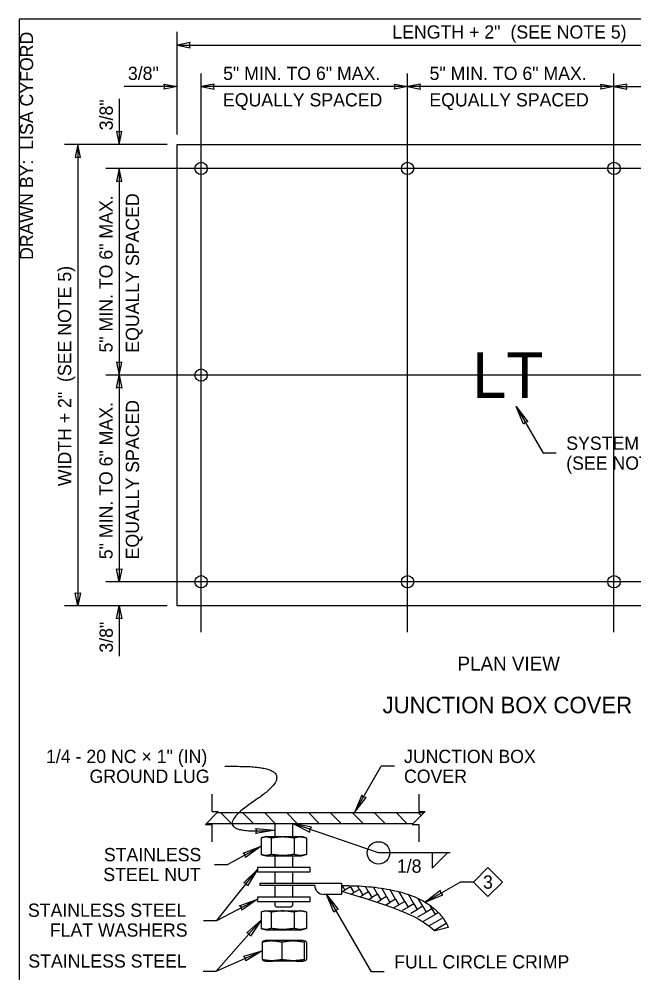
# Model space of a CAD drawing. Extents: x 99862 to 103680, y 99470 to 102076.
# Drawn here: x 99862 to 100605, y 100923 to 102076 of the extents above; entities that cross this region are included whole.
import ezdxf

# ---------------------------------------------------------------- set-up
doc = ezdxf.new("R2010")
doc.units = 0
for name, color, linetype in [('Level 1', 7, 'Continuous'), ('Level 10', 7, 'Continuous'), ('Level 11', 7, 'Continuous'), ('Level 13', 7, 'Continuous'), ('Level 15', 7, 'Continuous'), ('Level 16', 7, 'Continuous'), ('Level 20', 7, 'Continuous'), ('Level 62', 7, 'Continuous')]:
    doc.layers.add(name, color=color, linetype=linetype)

msp = doc.modelspace()

# ---------------------------------------------------------------- linework, layer by layer
at = {"layer": 'Level 1'}
for p, q in [((100101.6, 101116.4), (100351.5, 101116.4)), ((100105.5, 101116.4), (100118.7, 101103.3)), ((100132, 101116.4), (100145.2, 101103.3)), ((100158.6, 101116.4), (100171.7, 101103.3)), ((100185.1, 101116.4), (100198.2, 101103.3)), ((100211.6, 101116.4), (100224.8, 101103.3)), ((100238.1, 101116.4), (100251.3, 101103.3)), ((100264.6, 101116.4), (100277.8, 101103.3)), ((100291.1, 101116.4), (100304.3, 101103.3)), ((100317.7, 101116.4), (100330.8, 101103.3)), ((100344.2, 101116.4), (100347.8, 101112.8)), ((100088.4, 101103.3), (100338.3, 101103.3))]:
    msp.add_line(p, q, dxfattribs=at)
msp.add_lwpolyline([(99862, 99999.5), (103151, 99999.5), (103151, 102075.5), (99862, 102075.5)], close=True, dxfattribs=at)
msp.add_lwpolyline([(99862, 99999.5), (103151, 99999.5), (103151, 102075.5), (99862, 102075.5)], close=True, dxfattribs=at)
msp.add_lwpolyline([(99862, 99999.5), (103151, 99999.5), (103151, 102075.5), (99862, 102075.5)], close=True, dxfattribs=at)
at = {"layer": 'Level 10'}
for p, q in [((100171, 101103.3), (100171, 101087.4)), ((100192.9, 101087.4), (100192.9, 101103.3)), ((100155.1, 101085.9), (100154.4, 101085.6)), ((100154.4, 101085.6), (100154.4, 101065.9)), ((100160.5, 101087.4), (100155.1, 101085.9)), ((100160.5, 101087.4), (100203.4, 101087.4)), ((100166.8, 101085.6), (100166.8, 101065.9)), ((100194.4, 101085.6), (100194.4, 101065.9)), ((100208.8, 101085.9), (100203.4, 101087.4)), ((100208.8, 101085.9), (100209.5, 101085.6)), ((100209.5, 101085.6), (100209.5, 101065.9)), ((100154.3, 101065.9), (100160.5, 101064.2)), ((100208.8, 101065.7), (100209.5, 101065.9)), ((100160.5, 101064.2), (100203.4, 101064.2)), ((100171, 101064.2), (100171, 101050.3)), ((100192.9, 101050.3), (100192.9, 101064.2)), ((100203.4, 101064.2), (100208.8, 101065.7)), ((100171, 101045), (100171, 101031.2)), ((100192.9, 101031.2), (100192.9, 101045)), ((100171, 101028.5), (100171, 101014.4)), ((100192.9, 101014.4), (100192.9, 101028.5)), ((100171, 101009.1), (100171, 101004.2)), ((100192.9, 101004.2), (100192.9, 101009.1)), ((100160.5, 100997.9), (100155.1, 100996.4)), ((100160.5, 100997.9), (100203.4, 100997.9)), ((100173.3, 101002), (100171, 101004.2)), ((100190.6, 101002), (100173.3, 101002)), ((100192.9, 101004.2), (100190.6, 101002)), ((100208.8, 100996.4), (100203.4, 100997.9)), ((100155.1, 100996.4), (100154.4, 100996.2)), ((100154.4, 100996.2), (100154.4, 100976.5)), ((100166.8, 100996.2), (100166.8, 100976.5)), ((100194.4, 100996.2), (100194.4, 100976.5)), ((100208.8, 100996.4), (100209.5, 100996.2)), ((100209.5, 100996.2), (100209.5, 100976.5)), ((100154.3, 100976.5), (100160.5, 100974.7)), ((100160.5, 100974.7), (100203.4, 100974.7)), ((100203.4, 100974.7), (100208.8, 100976.3)), ((100208.8, 100976.2), (100209.5, 100976.5)), ((100155.7, 100959.8), (100157, 100960.9)), ((100155.7, 100959.8), (100155.7, 100938.8)), ((100159.8, 100961.7), (100156.9, 100960.9)), ((100179.7, 100959.8), (100179.7, 100938.8)), ((100208.3, 100960.9), (100205.5, 100961.7)), ((100206.5, 100959.8), (100206.5, 100938.8)), ((100209.5, 100959.8), (100208.3, 100960.9)), ((100209.5, 100959.8), (100209.5, 100938.8)), ((100155.7, 100938.8), (100157, 100937.8)), ((100156.9, 100937.8), (100159.8, 100937)), ((100205.5, 100937), (100208.3, 100937.8)), ((100209.5, 100938.8), (100208.3, 100937.8))]:
    msp.add_line(p, q, dxfattribs=at)
for centre, major_axis, start_param, end_param in [((100182.6, 100961.7), (22.9, 0), 0.625296, 3.141532), ((100182.6, 100961.7), (-14.1, 0), 0, 0.013106), ((100182.6, 100961.7), (22.9, 0), 0.00006, 0.625296), ((100182.6, 100937), (22.9, 0), 3.141653, 4.049582), ((100182.6, 100937), (22.9, 0), 0.625296, 3.141653), ((100182.6, 100937), (-14.1, 0), 0, 0.013106), ((100182.6, 100937), (-14.1, 0), 3.141593, 6.283185), ((100182.6, 100937), (22.9, 0), 5.37533, 6.283125), ((100182.6, 100937), (22.9, 0), 6.283125, 6.908482)]:
    msp.add_ellipse(centre, major_axis=major_axis, ratio=0.000017, start_param=start_param, end_param=end_param, dxfattribs=at)
for points in [[(100166.8, 101085.6), (100162.9, 101086.9), (100159, 101087.1), (100155.1, 101085.9)], [(100194.4, 101085.6), (100185.2, 101087), (100176, 101087), (100166.8, 101085.6)], [(100209.5, 101085.6), (100204.5, 101086.9), (100199.4, 101087.1), (100194.4, 101085.6)], [(100166.8, 101065.9), (100162.9, 101064.7), (100159, 101064.5), (100155.1, 101065.7)], [(100194.4, 101065.9), (100185.2, 101064.5), (100176, 101064.6), (100166.8, 101065.9)], [(100209.5, 101065.9), (100204.5, 101064.6), (100199.4, 101064.5), (100194.4, 101065.9)], [(100166.8, 100996.2), (100162.9, 100997.4), (100159, 100997.6), (100155.1, 100996.4)], [(100194.4, 100996.2), (100185.2, 100997.6), (100176, 100997.6), (100166.8, 100996.2)], [(100209.5, 100996.2), (100204.5, 100997.5), (100199.4, 100997.6), (100194.4, 100996.2)], [(100166.8, 100976.5), (100162.9, 100975.2), (100159, 100975), (100155.1, 100976.2)], [(100194.4, 100976.5), (100185.2, 100975.1), (100176, 100975.1), (100166.8, 100976.5)], [(100209.5, 100976.5), (100204.5, 100975.2), (100199.4, 100975), (100194.4, 100976.5)], [(100179.7, 100959.8), (100171.7, 100961.2), (100163.7, 100961.4), (100155.7, 100959.8)], [(100206.5, 100959.8), (100197.6, 100961.3), (100188.6, 100961.3), (100179.7, 100959.8)], [(100208.3, 100960.9), (100207.7, 100961.1), (100207.1, 100960.5), (100206.5, 100959.8)], [(100179.7, 100938.8), (100171.7, 100937.4), (100163.7, 100937.3), (100155.7, 100938.8)], [(100206.5, 100938.8), (100197.6, 100937.3), (100188.6, 100937.4), (100179.7, 100938.8)], [(100208.3, 100937.8), (100207.7, 100937.5), (100207.1, 100938.2), (100206.5, 100938.8)]]:
    msp.add_open_spline(points, degree=2, dxfattribs=at)
at = {"layer": 'Level 11'}
for p, q in [((100252.3, 101028.3), (100255.6, 101022.6)), ((100253, 101021.1), (100255.6, 101022.6)), ((100262.5, 101026.6), (100255.6, 101022.6)), ((100262.5, 101026.6), (100261.6, 101028.1)), ((100262.5, 101026.6), (100266.5, 101019.7)), ((100263.4, 101018), (100266.5, 101019.7)), ((100273.4, 101023.7), (100266.5, 101019.7)), ((100273.4, 101023.7), (100271.1, 101027.8)), ((100273.4, 101023.7), (100277.4, 101016.8)), ((100284.4, 101020.8), (100277.4, 101016.8)), ((100284.4, 101020.8), (100280.7, 101027.2)), ((100284.4, 101020.8), (100288.4, 101013.9)), ((100295.3, 101017.9), (100290.4, 101026.3)), ((100306.2, 101014.9), (100300.4, 101025)), ((100317.1, 101012), (100310.6, 101023.3)), ((100328.1, 101009.1), (100321.3, 101020.8)), ((100273.9, 101014.8), (100277.4, 101016.8)), ((100284.4, 101011.6), (100288.4, 101013.9)), ((100295.3, 101017.9), (100288.4, 101013.9)), ((100294.8, 101008.3), (100299.3, 101010.9)), ((100295.3, 101017.9), (100299.3, 101010.9)), ((100306.2, 101014.9), (100299.3, 101010.9)), ((100306.2, 101014.9), (100306.2, 101014.9)), ((100306.2, 101014.9), (100310.2, 101008)), ((100317.1, 101012), (100310.2, 101008)), ((100317.1, 101012), (100321.1, 101005.1)), ((100328.1, 101009.1), (100321.1, 101005.1)), ((100328.1, 101009.1), (100332.1, 101002.2)), ((100339, 101006.2), (100332.5, 101017.5)), ((100349.9, 101003.2), (100344.5, 101012.6)), ((100305.1, 101005.1), (100310.2, 101008)), ((100315.4, 101001.8), (100321.1, 101005.1)), ((100325.5, 100998.4), (100332.1, 101002.2)), ((100339, 101006.2), (100332.1, 101002.2)), ((100335.4, 100994.9), (100343, 100999.2)), ((100339, 101006.2), (100343, 100999.2)), ((100349.9, 101003.2), (100343, 100999.2)), ((100349.9, 101003.2), (100353.9, 100996.3)), ((100360.8, 101000.3), (100353.9, 100996.3)), ((100360.8, 101000.3), (100358.4, 101004.6)), ((100360.8, 101000.3), (100364.8, 100993.4)), ((100344.1, 100990.6), (100353.9, 100996.3)), ((100350.6, 100985.1), (100364.8, 100993.4)), ((100357.2, 100979.7), (100374, 100989.4)), ((100368.8, 100995.7), (100364.8, 100993.4)), ((100363.9, 100974.4), (100378.3, 100982.7)), ((100380.7, 100977.8), (100364.9, 100973.6))]:
    msp.add_line(p, q, dxfattribs=at)
for points, degree in [([(100251.8, 101028.3), (100358.6, 101028.3), (100380.7, 100977.8)], 2), ([(100251.8, 101021.5), (100339.2, 100995.2), (100347.2, 100987.7), (100364.9, 100973.6)], 3)]:
    msp.add_open_spline(points, degree=degree, dxfattribs=at)
at = {"layer": 'Level 13'}
for p, q in [((100153.5, 101028.5), (100153.5, 101031.2)), ((100153.5, 101031.2), (100162.9, 101031.2)), ((100162.9, 101028.5), (100153.5, 101028.5)), ((100162.9, 101031.2), (100199.6, 101031.2)), ((100199.6, 101028.5), (100162.9, 101028.5)), ((100199.6, 101031.2), (100205.6, 101031.2)), ((100205.6, 101028.5), (100199.6, 101028.5)), ((100205.6, 101031.2), (100217.4, 101031.2)), ((100219.3, 101028.5), (100205.6, 101028.5)), ((100217.4, 101031.2), (100251.8, 101031.2)), ((100251.8, 101031.2), (100251.8, 101017.6)), ((100251.8, 101017.6), (100230.2, 101017.6))]:
    msp.add_line(p, q, dxfattribs=at)
for points in [[(100150.1, 101050.3), (100150.1, 101045), (100213.8, 101045), (100213.8, 101050.3)], [(100150.1, 101014.4), (100150.1, 101009.1), (100213.8, 101009.1), (100213.8, 101014.4)]]:
    msp.add_lwpolyline(points, close=True, dxfattribs=at)
msp.add_arc((100230.2, 101028.5), 10.9, 180, 270, dxfattribs=at)
at = {"layer": 'Level 15'}
for p, q in [((100053, 101935.9), (100053, 102059.9)), ((100053, 102043.9), (100859.4, 102043.9)), ((100082, 101334.5), (100082, 102009.9)), ((100331.5, 101334.5), (100331.5, 102009.9)), ((100581, 101334.5), (100581, 102009.9)), ((100053, 101993.9), (99989, 101993.9)), ((100331.5, 101993.9), (100082, 101993.9)), ((100581, 101993.9), (100331.5, 101993.9)), ((100581, 101993.9), (100830.5, 101993.9)), ((99983, 101979), (99983, 101923.9)), ((100041, 101923.9), (99917, 101923.9)), ((99933, 101923.9), (99933, 101366.5)), ((100891.4, 101895), (99967, 101895)), ((99983, 101895), (99983, 101645.2)), ((100891.4, 101645.2), (99967, 101645.2)), ((99983, 101645.2), (99983, 101395.5)), ((100462.8, 101607.2), (100495.3, 101550.9)), ((100511.3, 101550.9), (100495.3, 101550.9)), ((100891.4, 101395.5), (99967, 101395.5)), ((100041, 101366.5), (99917, 101366.5)), ((99983, 101366.5), (99983, 101305.7)), ((100110.5, 101172.4), (100126.5, 101172.4)), ((100267.5, 101116.4), (100299.8, 101172.4)), ((100315.8, 101172.4), (100299.8, 101172.4)), ((100296.4, 101067.8), (100192.9, 101103.3)), ((100154.4, 101075.8), (100114.3, 101053.7)), ((100383, 101067.8), (100296.4, 101067.8)), ((100379.6, 101067.8), (100361.2, 101049.4)), ((100361.2, 101067.8), (100361.2, 101049.4)), ((100098.3, 101053.7), (100114.3, 101053.7)), ((100100.9, 100986.2), (100150.1, 101047.6)), ((100352.9, 101008.2), (100395.1, 101032.5)), ((100411.1, 101032.5), (100395.1, 101032.5)), ((100100.9, 100986.2), (100150.1, 101011.8)), ((100233.5, 101017.6), (100287.4, 100924.1)), ((100084.9, 100986.2), (100100.9, 100986.2)), ((100100.4, 100924.8), (100154.4, 100986.3)), ((100100.4, 100924.8), (100155.7, 100949.3)), ((100084.4, 100924.8), (100100.4, 100924.8)), ((100303.4, 100924.1), (100287.4, 100924.1))]:
    msp.add_line(p, q, dxfattribs=at)
for points in [[(100053, 102043.9), (100068.7, 102040.9), (100068, 102043.9), (100068.7, 102047)], [(100053, 101993.9), (100037.3, 101990.9), (100038, 101993.9), (100037.3, 101997)], [(100082, 101993.9), (100097.7, 101990.9), (100097, 101993.9), (100097.7, 101997)], [(100331.5, 101993.9), (100315.7, 101990.9), (100316.5, 101993.9), (100315.7, 101997)], [(100331.5, 101993.9), (100347.2, 101990.9), (100346.5, 101993.9), (100347.2, 101997)], [(100581, 101993.9), (100565.3, 101990.9), (100566, 101993.9), (100565.3, 101997)], [(100581, 101993.9), (100596.7, 101990.9), (100596, 101993.9), (100596.7, 101997)], [(99983, 101923.9), (99986.1, 101939.7), (99983, 101938.9), (99979.9, 101939.7)], [(99933, 101923.9), (99929.9, 101908.2), (99933, 101908.9), (99936.1, 101908.2)], [(99983, 101895), (99979.9, 101879.3), (99983, 101880), (99986.1, 101879.3)], [(99983, 101645.2), (99986.1, 101660.9), (99983, 101660.2), (99979.9, 101660.9)], [(99983, 101645.2), (99986.1, 101629.5), (99983, 101630.2), (99979.9, 101629.5)], [(100462.8, 101607.2), (100476.8, 101588.9), (100473.7, 101588.4), (100471.7, 101585.9)], [(99983, 101395.5), (99979.9, 101411.2), (99983, 101410.5), (99986.1, 101411.2)], [(99933, 101366.5), (99929.9, 101382.2), (99933, 101381.5), (99936.1, 101382.2)], [(99983, 101366.5), (99986.1, 101350.8), (99983, 101351.5), (99979.9, 101350.8)], [(100267.5, 101116.4), (100281.5, 101134.7), (100278.3, 101135.3), (100276.3, 101137.7)], [(100192.9, 101103.3), (100213.5, 101093), (100213.5, 101096.2), (100215.4, 101098.7)], [(100171, 101095.3), (100148.3, 101091.3), (100149.3, 101094.3), (100148.1, 101097.2)], [(100154.4, 101075.8), (100135.8, 101062.1), (100135.3, 101065.3), (100132.9, 101067.4)], [(100150.1, 101047.6), (100138.1, 101027.9), (100136.5, 101030.6), (100133.5, 101031.7)], [(100352.9, 101008.2), (100374.2, 101017), (100371.8, 101019), (100371.2, 101022.2)], [(100150.1, 101011.8), (100131.2, 100998.6), (100130.8, 101001.7), (100128.4, 101003.9)], [(100233.5, 101017.6), (100247.5, 100999.3), (100244.3, 100998.7), (100242.3, 100996.3)], [(100154.4, 100986.3), (100141.5, 100967.2), (100140, 100970), (100137.1, 100971.1)], [(100155.7, 100949.3), (100136.1, 100937.4), (100135.8, 100940.5), (100133.7, 100942.8)]]:
    msp.add_lwpolyline(points, close=True, dxfattribs=at)
for points in [[(100095.1, 101138.7), (100095.1, 101117.7), (100102.8, 101117.7), (100087.4, 101102.2), (100095.1, 101102.2), (100095.1, 101081.1)], [(100345, 101138.7), (100345, 101117.7), (100352.7, 101117.7), (100337.2, 101102.2), (100345, 101102.2), (100345, 101081.1)]]:
    msp.add_lwpolyline(points, dxfattribs=at)
msp.add_circle((100296.4, 101067.8), 13.5, dxfattribs=at)
msp.add_open_spline([(100126.5, 101172.4), (100209.5, 101172.4), (100082.6, 101088.2), (100171, 101095.3)], degree=2, dxfattribs=at)
at = {"layer": 'Level 16'}
msp.add_lwpolyline([(100053, 101923.9), (100859.4, 101923.9), (100859.4, 101366.5), (100053, 101366.5)], close=True, dxfattribs=at)
for centre in [(100082, 101895), (100331.5, 101895), (100581, 101895), (100082, 101645.2), (100082, 101645.2), (100082, 101395.5), (100331.5, 101395.5), (100581, 101395.5)]:
    msp.add_circle(centre, 7.5, dxfattribs=at)
at = {"layer": 'Level 20'}
msp.add_lwpolyline([(100428.6, 101050), (100446.2, 101032.5), (100428.6, 101014.9), (100411.1, 101032.5)], close=True, dxfattribs=at)

# ---------------------------------------------------------------- texts
for s, height, p in [('(SEE NOTE 5)', 16, (100455.9, 102051.9)), ('LENGTH + 2" ', 16, (100313.1, 102051.9)), ('3/8"', 16, (99993.5, 102001.9)), ('LT', 55, (100410, 101617.7)), ('PLAN VIEW', 17, (100391.9, 101288)), ('JUNCTION BOX COVER', 20, (100301.3, 101236.5)), ('1/4 - 20 NC × 1" (IN)', 16, (99894.6, 101176.4)), ('JUNCTION BOX', 16, (100327.2, 101176.4)), ('GROUND LUG', 16, (99947.2, 101152.4)), ('COVER', 16, (100327.2, 101152.4)), ('STAINLESS', 16, (99964.5, 101057.7)), ('1/8', 16, (100318.6, 101043.8)), ('STEEL NUT', 16, (99963.8, 101033.7)), ('3', 16, (100422.7, 101024.5)), ('STAINLESS STEEL', 16, (99872.7, 100990.5)), ('FLAT WASHERS', 16, (99899.2, 100966.5)), ('STAINLESS STEEL', 16, (99873.2, 100929.1))]:
    msp.add_text(s, height=height, dxfattribs=at).set_placement(p)
for s, rotation, p in [('5" MIN. TO 6" MAX.', 360, (100108.6, 102001.9)), ('5" MIN. TO 6" MAX.', 360, (100358.1, 102001.9)), ('3/8"', 90, (99975.3, 101941.1)), ('EQUALLY SPACED', 360, (100108.4, 101969.9)), ('EQUALLY SPACED', 360, (100357.9, 101969.9)), ('EQUALLY SPACED', 90, (100007, 101672.3)), ('5" MIN. TO 6" MAX.', 90, (99975, 101672.5)), ('(SEE NOTE 5)', 90, (99925, 101636.9)), ('WIDTH + 2" ', 90, (99925, 101511)), ('5" MIN. TO 6" MAX.', 90, (99975, 101422.7)), ('EQUALLY SPACED', 90, (100007, 101422.5)), ('SYSTEM IDENTIFICATION', 360, (100523.3, 101554.9)), ('(SEE NOTE 4)', 360, (100523.3, 101530.9)), ('3/8"', 90, (99975.3, 101309.8)), ('FULL CIRCLE CRIMP ', 360, (100315.4, 100928.1))]:
    msp.add_text(s, height=16, rotation=rotation, dxfattribs=at).set_placement(p)
at = {"layer": 'Level 62'}
msp.add_text('DRAWN BY:  LISA CYFORD', height=16, rotation=90, dxfattribs=at).set_placement((99879, 101784.4))

doc.saveas('drawing.dxf')
